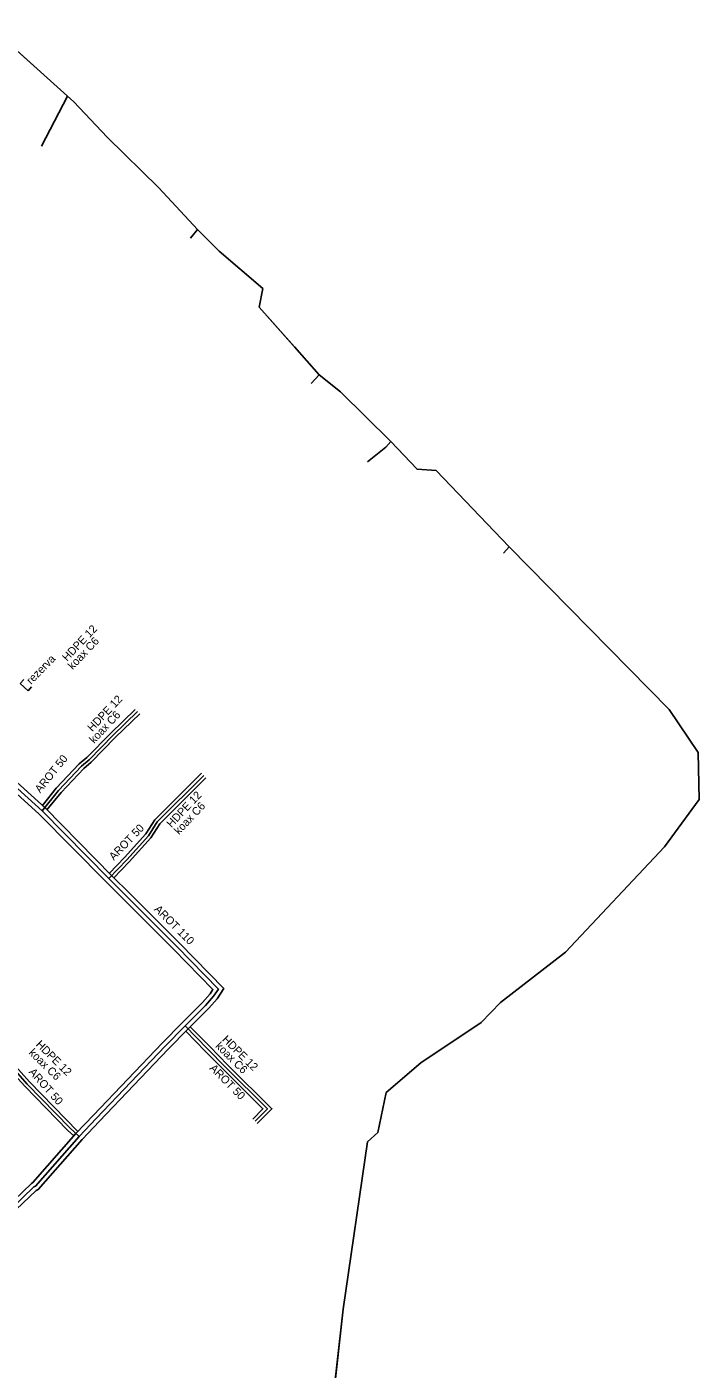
# Model space of a CAD drawing. Extents: x -651943 to -618711, y -1138561 to -1100552.
# Drawn here: x -640696 to -640633, y -1114827.6 to -1114701.8 of the extents above; entities that cross this region are included whole.
import ezdxf

# ---------------------------------------------------------------- set-up
doc = ezdxf.new("R2010")
doc.units = 0
for name, color, linetype in [('KT optika', 7, 'Continuous'), ('KT trasa', 7, 'Continuous'), ('KT zařízení', 7, 'Continuous')]:
    doc.layers.add(name, color=color, linetype=linetype)

# ---------------------------------------------------------------- blocks, each defined once
blk = doc.blocks.new('TVREZ')
at = {"layer": 'KT zařízení'}
for p, q in [((-0.05, 0.05), (0, 0.05)), ((0, -0.05), (0, 0.05)), ((-0.05, -0.05), (0, -0.05))]:
    blk.add_line(p, q, dxfattribs=at)

msp = doc.modelspace()

# ---------------------------------------------------------------- linework, layer by layer
at = {"layer": 'KT optika'}
for points in [[(-640699.46, -1114701.79), (-640691.64, -1114708.83), (-640688.52, -1114712.14), (-640683.66, -1114716.87), (-640680.04, -1114720.78), (-640678.02, -1114722.83), (-640673.91, -1114726.32), (-640674.25, -1114728.06), (-640668.63, -1114734.42), (-640666.63, -1114735.99), (-640661.92, -1114740.66), (-640659.47, -1114743.26), (-640657.68, -1114743.38), (-640650.85, -1114750.54), (-640635.85, -1114765.77), (-640633.14, -1114769.81), (-640633.04, -1114774.22), (-640636.28, -1114778.65), (-640645.56, -1114788.52), (-640651.64, -1114793.24), (-640653.46, -1114795.13), (-640659.11, -1114798.89), (-640662.38, -1114801.69), (-640663.15, -1114805.42), (-640664.11, -1114806.32), (-640666.38, -1114822), (-640667.58, -1114832.49)], [(-640694.61, -1114775.29), (-640693.06, -1114773.37), (-640690.91, -1114771.08), (-640690.21, -1114770.49), (-640687.96, -1114768.2), (-640685.67, -1114765.98)], [(-640701.23, -1114769.31), (-640694.61, -1114775.29), (-640688.36, -1114781.64), (-640686.64, -1114783.35), (-640681.97, -1114788.01), (-640678.09, -1114791.99), (-640678.53, -1114792.67), (-640679.28, -1114793.52), (-640681.21, -1114795.45), (-640683.07, -1114797.33), (-640689.51, -1114804.09), (-640691.14, -1114805.81), (-640695.21, -1114810.46), (-640695.38, -1114810.54), (-640698.58, -1114813.59)], [(-640688.36, -1114781.64), (-640686.66, -1114779.87), (-640684.65, -1114777.62), (-640683.81, -1114776.31), (-640679.46, -1114771.97)], [(-640681.21, -1114795.45), (-640679.11, -1114797.59), (-640677.41, -1114799.32), (-640673.49, -1114803.21), (-640674.65, -1114804.38)], [(-640691.14, -1114805.81), (-640692, -1114805), (-640696, -1114800.9), (-640697.54, -1114799.16), (-640697.91, -1114798.9), (-640698.04, -1114798.59), (-640699.06, -1114798.11), (-640699.58, -1114797.69), (-640699.59, -1114797.44)]]:
    msp.add_lwpolyline(points, dxfattribs=at)
at = {"layer": 'KT trasa'}
for p, q in [((-640699.46, -1114701.79), (-640691.64, -1114708.83)), ((-640692.21, -1114708.29), (-640694.67, -1114712.96)), ((-640691.64, -1114708.83), (-640688.52, -1114712.14)), ((-640688.52, -1114712.14), (-640683.66, -1114716.87)), ((-640683.66, -1114716.87), (-640680.04, -1114720.78)), ((-640680.04, -1114720.78), (-640680.71, -1114721.59)), ((-640680.04, -1114720.78), (-640678.02, -1114722.83)), ((-640678.02, -1114722.83), (-640673.91, -1114726.32)), ((-640673.91, -1114726.32), (-640674.25, -1114728.06)), ((-640674.25, -1114728.06), (-640670.94, -1114731.79)), ((-640670.94, -1114731.79), (-640668.63, -1114734.42)), ((-640668.63, -1114734.42), (-640669.38, -1114735.21)), ((-640668.63, -1114734.42), (-640666.63, -1114735.99)), ((-640666.63, -1114735.99), (-640661.92, -1114740.66)), ((-640662.4, -1114741.19), (-640664.12, -1114742.57)), ((-640661.92, -1114740.66), (-640662.4, -1114741.19)), ((-640661.92, -1114740.66), (-640659.47, -1114743.26)), ((-640659.47, -1114743.26), (-640657.68, -1114743.38)), ((-640657.68, -1114743.38), (-640650.85, -1114750.54)), ((-640650.85, -1114750.54), (-640651.38, -1114751.12)), ((-640650.85, -1114750.54), (-640635.85, -1114765.77)), ((-640635.85, -1114765.77), (-640633.14, -1114769.81)), ((-640633.14, -1114769.81), (-640633.04, -1114774.22)), ((-640633.04, -1114774.22), (-640636.28, -1114778.65)), ((-640636.28, -1114778.65), (-640645.56, -1114788.52)), ((-640645.56, -1114788.52), (-640651.64, -1114793.24)), ((-640651.64, -1114793.24), (-640653.46, -1114795.13)), ((-640653.46, -1114795.13), (-640659.11, -1114798.89)), ((-640659.11, -1114798.89), (-640662.38, -1114801.69)), ((-640662.38, -1114801.69), (-640663.15, -1114805.42)), ((-640663.15, -1114805.42), (-640664.11, -1114806.32)), ((-640664.11, -1114806.32), (-640666.38, -1114822)), ((-640666.38, -1114822), (-640667.58, -1114832.49))]:
    msp.add_line(p, q, dxfattribs=at)
for points in [[(-640694.61, -1114775.29), (-640693.06, -1114773.37), (-640690.91, -1114771.08), (-640690.21, -1114770.49), (-640687.96, -1114768.2), (-640685.67, -1114765.98)], [(-640701.23, -1114769.31), (-640694.61, -1114775.29), (-640688.36, -1114781.64), (-640686.64, -1114783.35), (-640681.97, -1114788.01), (-640678.09, -1114791.99), (-640678.53, -1114792.67), (-640679.28, -1114793.52), (-640681.21, -1114795.45), (-640683.07, -1114797.33), (-640689.51, -1114804.09), (-640691.14, -1114805.81), (-640695.21, -1114810.46), (-640695.38, -1114810.54), (-640698.58, -1114813.59)], [(-640688.36, -1114781.64), (-640686.66, -1114779.87), (-640684.65, -1114777.62), (-640683.81, -1114776.31), (-640679.46, -1114771.97)], [(-640681.21, -1114795.45), (-640679.11, -1114797.59), (-640677.41, -1114799.32), (-640673.49, -1114803.21), (-640674.65, -1114804.38)], [(-640691.14, -1114805.81), (-640692, -1114805), (-640696, -1114800.9), (-640697.54, -1114799.16), (-640697.91, -1114798.9), (-640698.04, -1114798.59), (-640699.06, -1114798.11), (-640699.58, -1114797.69), (-640699.59, -1114797.44)]]:
    msp.add_lwpolyline(points, dxfattribs=at)
at = {"layer": 'KT zařízení'}
for points in [[(-640694.58, -1114774.78), (-640693.29, -1114773.17), (-640691.12, -1114770.86), (-640690.41, -1114770.27), (-640688.17, -1114767.99), (-640685.88, -1114765.77)], [(-640694.15, -1114775.19), (-640692.83, -1114773.57), (-640690.7, -1114771.3), (-640690.01, -1114770.71), (-640687.75, -1114768.41), (-640685.46, -1114766.2)], [(-640701.51, -1114769.6), (-640694.89, -1114775.58), (-640688.64, -1114781.92), (-640686.92, -1114783.63), (-640682.25, -1114788.29), (-640678.6, -1114792.04), (-640678.85, -1114792.43), (-640679.57, -1114793.25), (-640681.49, -1114795.17), (-640683.36, -1114797.05), (-640689.8, -1114803.81), (-640691.44, -1114805.54), (-640695.46, -1114810.13), (-640695.61, -1114810.21), (-640698.88, -1114813.33)], [(-640700.95, -1114769.02), (-640694.33, -1114775), (-640688.08, -1114781.36), (-640686.36, -1114783.07), (-640681.69, -1114787.73), (-640677.58, -1114791.94), (-640678.21, -1114792.91), (-640678.99, -1114793.79), (-640680.93, -1114795.73), (-640682.78, -1114797.61), (-640689.22, -1114804.37), (-640690.84, -1114806.08), (-640694.96, -1114810.79), (-640695.15, -1114810.87), (-640698.28, -1114813.85)], [(-640688.29, -1114781.14), (-640686.88, -1114779.67), (-640684.89, -1114777.44), (-640684.05, -1114776.12), (-640679.67, -1114771.76)], [(-640687.87, -1114781.56), (-640686.44, -1114780.07), (-640684.41, -1114777.8), (-640683.58, -1114776.5), (-640679.25, -1114772.18)], [(-640681.14, -1114795.95), (-640679.32, -1114797.8), (-640677.62, -1114799.53), (-640673.92, -1114803.21), (-640674.86, -1114804.17)], [(-640680.72, -1114795.52), (-640678.9, -1114797.38), (-640677.2, -1114799.11), (-640673.07, -1114803.21), (-640674.44, -1114804.59)], [(-640691.63, -1114805.76), (-640692.21, -1114805.21), (-640696.22, -1114801.1), (-640697.74, -1114799.39), (-640698.15, -1114799.1), (-640698.27, -1114798.81), (-640699.22, -1114798.37), (-640699.87, -1114797.84), (-640699.89, -1114797.45)], [(-640691.25, -1114805.34), (-640695.78, -1114800.7), (-640697.34, -1114798.94), (-640697.67, -1114798.7), (-640697.81, -1114798.37), (-640698.9, -1114797.85), (-640699.29, -1114797.54), (-640699.29, -1114797.43)]]:
    msp.add_lwpolyline(points, dxfattribs=at)

# ---------------------------------------------------------------- block references
at = {"layer": 'KT zařízení', "xscale": 10.000001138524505, "yscale": 10.000001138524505, "rotation": -133.03510450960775}
msp.add_blockref('TVREZ', (-640696.29, -1114763.69), dxfattribs=at)

# ---------------------------------------------------------------- texts
at = {"layer": 'KT zařízení'}
for s, rotation, p in [('HDPE 12', 46.5703, (-640692.26, -1114761.32)), ('koax C6', 46.5703, (-640691.73, -1114762.1)), ('rezerva', 45.5673, (-640695.63, -1114763.48)), ('HDPE 12', 46.5703, (-640689.9, -1114767.91)), ('koax C6', 46.5703, (-640689.73, -1114769.02)), ('AROT 50', 51.0841, (-640694.78, -1114773.66)), ('HDPE 12', 46.5703, (-640682.48, -1114776.91)), ('koax C6', 46.5703, (-640681.78, -1114777.56)), ('AROT 50', 46.1521, (-640687.88, -1114779.98)), ('AROT 110', 315.0614, (-640684.15, -1114784.56)), ('HDPE 12', 315.2859, (-640677.79, -1114796.78)), ('koax C6', 315.2859, (-640695.91, -1114798.02)), ('HDPE 12', 315.2859, (-640695.25, -1114797.25)), ('koax C6', 315.2859, (-640678.42, -1114797.4)), ('AROT 50', 314.5152, (-640678.96, -1114799.46)), ('AROT 50', 311.5182, (-640695.9, -1114799.8))]:
    msp.add_text(s, height=0.75, rotation=rotation, dxfattribs=at).set_placement(p)

doc.saveas('drawing.dxf')
